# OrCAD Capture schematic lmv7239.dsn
size A
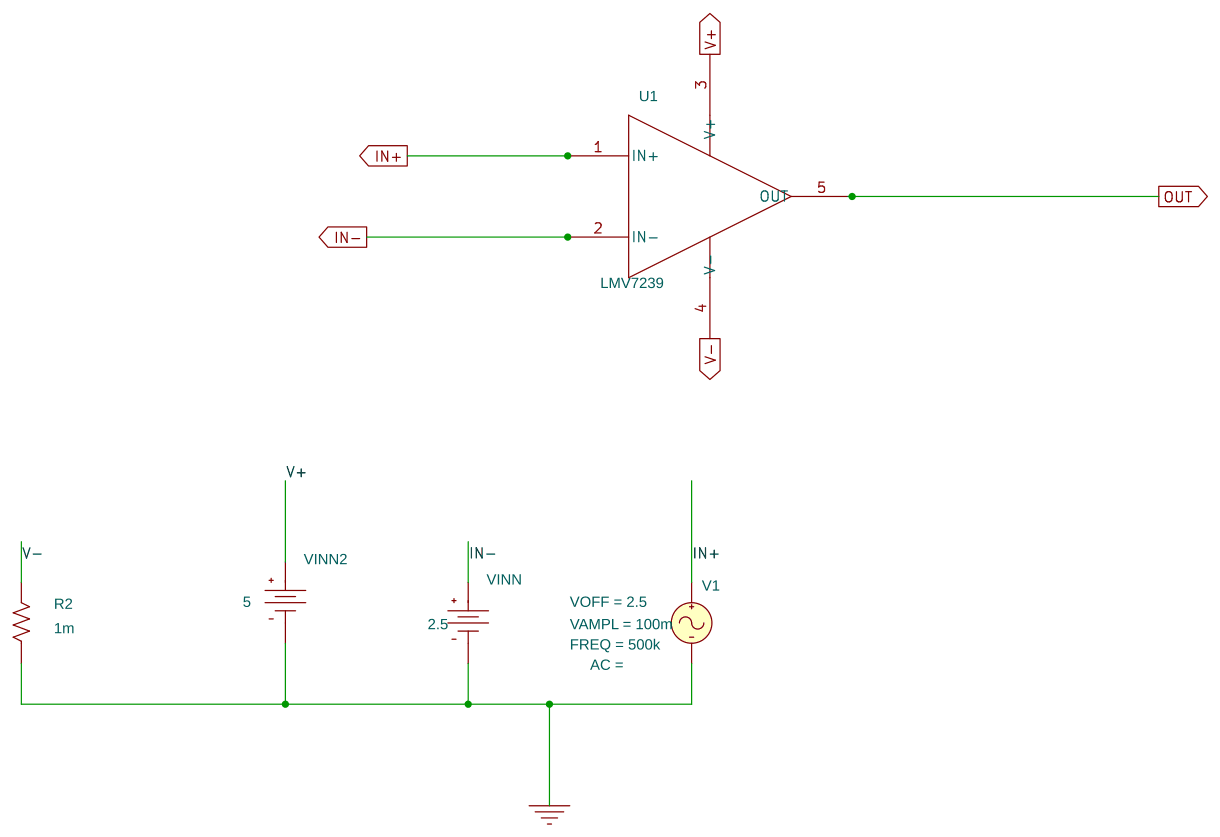
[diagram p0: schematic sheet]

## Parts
R2  1m  [AXRC05]
U1  LMV7239
V1  VSIN
VINN  VDC
VINN2  VDC

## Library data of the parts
R2 = R
U1 = LMV7239_0
V1 = VSIN: FREQ: 500k; VAMPL: 100m; VOFF: 2.5
VINN = VDC: DC: 2.5
VINN2 = VDC: DC: 5

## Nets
0: R2.1 V1.2(-) VINN.1(-) VINN2.1(-)
IN+: U1.1(IN+) V1.1(+)
IN-: U1.2(IN-) VINN.0(+)
OUT: U1.5(OUT)
V+: U1.3(V+) VINN2.0(+)
V-: R2.2 U1.4(V-)
